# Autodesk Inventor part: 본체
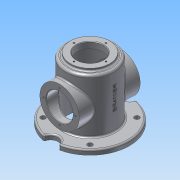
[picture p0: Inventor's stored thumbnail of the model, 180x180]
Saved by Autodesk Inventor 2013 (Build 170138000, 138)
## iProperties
Created: 2018-04
Part Number: 본체
Material: 알루미늄 6061
Document SubType Name: Modeling
Designer: Administrator
Density: 2.71 g/cm^3
Mass: 1151.24 g
Surface Area: 1200.36 cm^2
Volume: 424.812 cm^3
Author: Administrator
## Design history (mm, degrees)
sketch "스케치1"
  geometry: C1 r 50 at (0, 0); 1 further point
  constraints: 1 centre point, 1 coincident
  dimensions: "d0" = 100 diameter of C1
extrude "돌출1" new body sketch "스케치1" distance "d1" = 128; taper "d2" = 0 deg
feature "쉘1" dims "d3" = 5, "d87" = 8
node "작업 평면1"
sketch "스케치2"
  geometry: C1 r 50 at (0, 0) reference; C2 r 80 at (0, 0); 1 further point
  constraints: 1 centre point, 1 coincident
  dimensions: "d5" = 160 diameter of C2
extrude "돌출2" join sketch "스케치2" distance "d7" = 10; taper "d8" = 0 deg
sketch "스케치3"
  geometry: C1 r 50 at (0, 0) reference; C2 r 40 at (0, 0)
  constraints: 1 centre point, 1 coincident
  dimensions: "d9" = 80 diameter of C2
extrude "돌출3" join sketch "스케치3" distance "d10" = 5; taper "d11" = 0 deg
hole "구멍1" diameter "d14" = 54; stored, may be unused: countersink angle "d18" = 90 deg, drill point angle "d20" = 118 deg; dims "d12" = 10, "d13" = 10, "d15" = 6, "d16" = 4, "d17" = 2, "d19" = 8
node "작업 평면2"
sketch "스케치4"
  geometry: L1 (-80, 8)-(80, 8) reference; C1 r 40 at (0, 68); 1 further point
  constraints: 1 centre point, 1 vertical alignment
  dimensions: "d22" = 80 diameter of C1; "d24" = 60 distance from line of L1 C1.centre
extrude "돌출4" join sketch "스케치4" stored distance "d25" = 5; taper "d26" = 0 deg
hole "구멍2" diameter "d29" = 54; stored, may be unused: countersink angle "d33" = 90 deg, drill point angle "d35" = 118 deg; dims "d27" = 10, "d28" = 10, "d30" = 6, "d31" = 4, "d32" = 2, "d34" = 8
sketch "스케치5"
  geometry: C1 r 27 at (0, 0) reference; 2 further points
  constraints: 1 vertical alignment
  dimensions: "d36" = 32.5 distance of C1.centre point (0, 32.5)
hole "구멍3" sketch "스케치5" at (0, 32.5) diameter "d37" = 3.242; stored, may be unused: countersink angle "d41" = 90 deg, drill point angle "d43" = 118 deg; dims "d38" = 8, "d39" = 4, "d40" = 2, "d42" = 10
sketch "스케치6"
  geometry: C1 r 27 at (0, 0) reference; 1 further point
  constraints: 1 vertical alignment
  dimensions: "d47" = 32.5 distance of C1.centre point (0, 32.5)
hole "구멍4" sketch "스케치6" at (0, 32.5) diameter "d48" = 3.242; stored, may be unused: countersink angle "d52" = 90 deg, drill point angle "d54" = 118 deg; dims "d49" = 8, "d50" = 4, "d51" = 2, "d53" = 10
sketch "스케치7"
  geometry: L1 (-50, 0)-(0, 0); L2 (0, 0)-(-47.73, 47.73); C1 r 80 at (0, 0) reference; 2 further points
  constraints: 4 end point, 1 coincident, 1 horizontal, 1 horizontal alignment, 1 other
  dimensions: "d58" = 67.5 distance of L1.end L2.end; "d59" = 45 deg angle of L1 L2
hole "구멍5" sketch "스케치7" at (-47.73, 47.73) diameter "d60" = 10; stored, may be unused: countersink angle "d64" = 90 deg, drill point angle "d66" = 118 deg; dims "d61" = 8, "d62" = 4, "d63" = 2, "d65" = 10
sketch "스케치8"
  geometry: C1 r 50 at (0, 0) reference; C2 r 15 at (0, 80); 1 further point
  constraints: 2 vertical alignment, 1 centre point, 1 other
  dimensions: "d70" = 30 diameter of C2
extrude "돌출5" cut sketch "스케치8" stored distance "d71" = 5; taper "d72" = 0 deg
node "작업 평면3"
sketch "스케치9"
  geometry: L1 (-78.594, 8)-(78.594, 8) reference; 2 further points
  constraints: 1 vertical alignment, 1 other
  dimensions: "d77" = 70 distance from line of L1 point (0, 78)
feature "엠보싱1" sketch "스케치9" dims "d78" = 0.5, "d79" = 0
fillet "모깎기1" dims "d80" = 5
fillet "모깎기2" dims "d81" = 3
fillet "모깎기3" dims "d82" = 3
chamfer "모따기1" distance "d83" = 1; stored, may be unused: second distance "d84" = 2, angle "d85" = 45 deg
fillet "모깎기4" dims "d86" = 3
chamfer "모따기2" distance "d88" = 1; stored, may be unused: second distance "d89" = 2, angle "d90" = 45 deg
node "솔리드1"
pattern_circular "원형 패턴1" dims angle "d45" = 360 deg
mirror "대칭1"
pattern_circular "원형 패턴2" dims angle "d56" = 360 deg
pattern_circular "원형 패턴3" dims angle "d68" = 360 deg
pattern_circular "원형 패턴4" dims angle "d74" = 360 deg
other parameters: "d4" = 8, "d21" = 62, "d76" = 83.25
